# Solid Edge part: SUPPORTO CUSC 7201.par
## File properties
Subject: SUPPORTO CUSC 7201
Author: f_grande
Template: Normal.par
Last saved by: f_grande
Revision: 12
Application: Solid Edge
Densità: 750,000 kg/m^3
Precisione: 0,990
Tipo di contenuto documento: 0
Document Number: KR0131
Material: MDF
Stile della faccia: Marroncino
Coef. of Thermal Exp: 0.0
Thermal Conductivity: 0.0
Specific Heat: 0.0
Modulus of Elasticity: 0.0
Poisson's Ratio: 0.0
Yield Stress: 0.0
Ultimate Stress: 0.0
Elongation: 0.0
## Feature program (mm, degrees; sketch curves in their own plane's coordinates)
sketch for "unnamed Protrusion 1" plane through (0, 0, 0) normal (0, -1, 0) x-axis (1, 0, 0)
  line (-35.0443, 29.8388) -> (24.9557, 29.8388)
  line (24.9557, 29.8388) -> (24.9557, -30.1612)
  line (24.9557, -30.1612) -> (-35.0443, -30.1612)
  line (-35.0443, -30.1612) -> (-35.0443, 29.8388)
  dimension (linear) = 35.0443
  dimension (linear) = 35.0443
extrude "unnamed Protrusion 1" add finite 19 along -normal
sketch for "Foro_6" plane through (-7.5443, -3, 2.3388) normal (0, -1, 0) x-axis (1, 0, 0)
hole "Foro_6" diameter 32 through
sketch for "Foro_7" plane through (-7.5443, 19, 2.3388) normal (0, 1, 0) x-axis (-1, 0, 0)
hole "Foro_7" diameter 6 through
sketch for "unnamed Hole 1" plane through (-7.5443, 19, 2.3388) normal (0, 1, 0) x-axis (-1, 0, 0)
  hole centre (21.07, 21.07) bore radius 3
hole "unnamed Hole 1" through
sketch for "unnamed Hole 2" plane through (-7.5443, 19, 2.3388) normal (0, 1, 0) x-axis (-1, 0, 0)
  hole centre (21.07, -26.07) bore radius 3
hole "unnamed Hole 2" through
sketch for "unnamed Hole 3" plane through (-7.5443, 19, 2.3388) normal (0, 1, 0) x-axis (-1, 0, 0)
hole "unnamed Hole 3" through
pattern "unnamed Pattern 1" of "Foro_7", "unnamed Hole 1", "unnamed Hole 2", "unnamed Hole 3"
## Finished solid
Body 1: solid body, 11 faces, 22 edges, 8 vertices.
  Faces by surface: plane 6, cylinder 5
  Edges by curve: line 12, circle 10
Bounding box of the edges (mm): 60.000 x 19.000 x 60.000, from (-35.0443, 0, -30.1612) to (24.9557, 19, 29.8388).
Cylindrical faces by radius (mm): R3 x4, R16 x1
Planar faces by outward normal: +x 1, +y 1, +z 1, -x 1, -y 1, -z 1
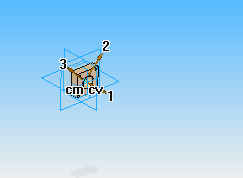
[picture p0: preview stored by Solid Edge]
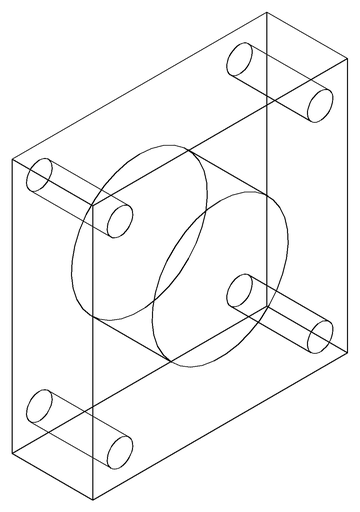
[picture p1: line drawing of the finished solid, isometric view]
